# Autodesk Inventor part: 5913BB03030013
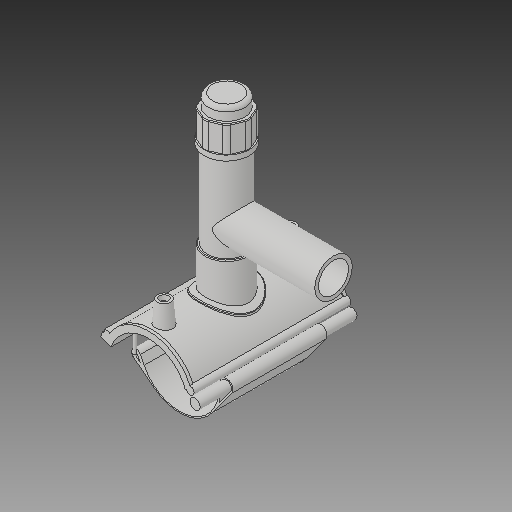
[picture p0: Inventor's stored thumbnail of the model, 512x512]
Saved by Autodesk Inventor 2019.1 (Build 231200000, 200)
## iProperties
Created: 2017-07
Part Number: 5913BB03030013
Material: Generic
Description: PLASSON TAPPING SADDLE 3''IPS x 1 1/4''IPS
Document SubType Name: Modeling
Designer: KIM
Mass: 1712.7 g
Surface Area: 2671.49 cm^2
Volume: 1712.7 cm^3
Density: 1 g/cm^3
Appearance: Default
Author: KIM
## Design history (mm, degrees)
derived "5913B.ipt"
feature "Solid1::5913B.ipt"
feature "Solid2::5913B.ipt"
feature "Solid4::5913B.ipt"
feature "Solid5::5913B.ipt"
tag "TaggingFeature1"
body "Solid1"
body "Solid2"
other parameters: "d0" = 88.7, "d2" = 208.407, "d3" = 22.175, "d4" = 176.022, "d5" = 0, "d6" = 0.1, "d8" = 0, "d40" = 52.58136, "d41" = 62.09, "d43" = 0, "d45" = 0, "d47" = 156.1722, "d78" = 74.35, "d79" = 15, "d80" = 70.4088, "d82" = 5 deg, "d84" = 4, "d85" = 14, "d86" = 0, "d87" = 3, "d88" = 0, "d96" = 103.14036, "d97" = 3.52044, "d98" = 0, "d102" = 0.887, "d120" = 140 deg, "d121" = 24.228, "d122" = 20 deg, "d123" = 252.795, "d124" = 60.6708, "d126" = 0, "d153" = 176.022, "d154" = 0, "d159" = 2.4836, "d162" = 105.6132, "d163" = 0, "d164" = 44.35, "d169" = 4.0905, "d170" = 3.7254, "d172" = 0, "d173" = 1, "d175" = 44.35, "d176" = 20 deg, "d177" = 6.209, "d178" = 12.418, "d180" = 0, "d183" = 4.9672, "d184" = 4.9672, "d187" = 50.559, "d188" = 3.7254, "d189" = 6.209, "d190" = 0, "d191" = 75.8385, "d193" = 3.1932, "d194" = 1.5966, "d195" = 90 deg, "d197" = 0, "d199" = 0, "d200" = 6.209, "d202" = 0, "d203" = 194.818, "d204" = 48.36811, "d205" = 35.63966, "d206" = 43.27673, "d207" = 146.1135, "d208" = 151.95804, "d209" = 181.18074, "d210" = 43.78587, "d211" = 50.9138, "d212" = 40.73104, "d213" = 48.492, "d216" = 0, "d217" = 8.87, "d218" = 4.435, "d219" = 0.887, "d222" = 88.7, "d224" = 0, "d230" = 0.887, "d257" = 119.28, "d258" = 119.888, "d259" = 33.68, "d260" = 42.1, "d263" = 138.938, "d265" = 0, "d267" = 13.00006, "d268" = 2.60001, "d269" = 2.60001, "d271" = 2.60001, "d273" = 0, "d274" = 23.56194, "d275" = 70.96, "d277" = 35.48, "d278" = 141.92, "d280" = 0, "d281" = 88.7, "d283" = 0, "d285" = 0, "d290" = 8.87, "d291" = 11.531, "d293" = 48.785, "d294" = 45.6805, "d296" = 13.305, "d297" = 10.644, "d_" = 88.7, "B_" = 138.938, "L_" = 176.022, "d_t" = 6, "H_2" = 194.818, "H_1" = 74.93, "d_1" = 42.1, "H_" = 119.888, "d1" = 101.118, "d192" = 3.1932
